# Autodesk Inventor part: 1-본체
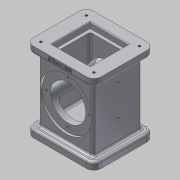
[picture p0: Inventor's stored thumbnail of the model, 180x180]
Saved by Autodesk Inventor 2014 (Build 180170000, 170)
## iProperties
Created: 2017-08
Part Number: 1-본체
Material: 알루미늄 6061
Document SubType Name: Modeling
Designer: 601-04
Density: 2.71 g/cm^3
Appearance: 알루미늄 - 평지
Mass: 871.037 g
Surface Area: 645.524 cm^2
Volume: 321.416 cm^3
Author: 601-04
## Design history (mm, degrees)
sketch "스케치1"
  geometry: L1 (-46, 41)-(46, 41); L2 (46, 41)-(46, -41); L3 (46, -41)-(-46, -41); L4 (-46, -41)-(-46, 41); L5 (-46, 41)-(46, -41); L6 (46, 41)-(-46, -41); 1 further point
  constraints: 12 end point, 2 midpoint, 2 parallel, 1 horizontal, 1 perpendicular
  dimensions: "d0" = 92 distance of L2.end L3.end; "d1" = 82 distance of L1.end L2.end
extrude "돌출1" new body sketch "스케치1" distance "d2" = 10; taper "d3" = 0 deg
sketch "스케치2"
  geometry: L1 (-37, 33)-(37, 33); L2 (37, 33)-(37, -33); L3 (37, -33)-(-37, -33); L4 (-37, -33)-(-37, 33); L5 (-37, 33)-(37, -33); L6 (37, 33)-(-37, -33); 1 further point
  constraints: 12 end point, 2 midpoint, 2 parallel, 1 horizontal, 1 perpendicular
  dimensions: "d4" = 74 distance of L2.end L3.end; "d5" = 66 distance of L1.end L2.end
extrude "돌출2" join sketch "스케치2" distance "d6" = 88; taper "d7" = 0 deg
sketch "스케치3"
  geometry: L1 (-46, 41)-(46, 41); L2 (46, 41)-(46, -41); L3 (46, -41)-(-46, -41); L4 (-46, -41)-(-46, 41); L5 (-46, 41)-(46, -41); L6 (46, 41)-(-46, -41); 1 further point
  constraints: 12 end point, 2 midpoint, 2 parallel, 1 horizontal, 1 perpendicular
  dimensions: "d8" = 92 distance of L2.end L3.end; "d9" = 82 distance of L1.end L2.end
extrude "돌출3" join sketch "스케치3" distance "d10" = 10; taper "d11" = 0 deg
sketch "스케치4"
  geometry: L1 (-22, 22)-(22, 22); L2 (22, 22)-(22, -22); L3 (22, -22)-(-22, -22); L4 (-22, -22)-(-22, 22); L5 (-22, 22)-(22, -22); L6 (22, 22)-(-22, -22); 1 further point
  constraints: 12 end point, 2 midpoint, 2 parallel, 1 horizontal, 1 perpendicular
  dimensions: "d12" = 44 distance of L2.end L3.end; "d13" = 44 distance of L1.end L2.end
extrude "돌출4" cut sketch "스케치4" distance "d14" = 82; taper "d15" = 0 deg
sketch "스케치5"
  geometry: L1 (26, 26)-(-26, 26); L2 (-26, 26)-(-26, -26); L3 (-26, -26)-(26, -26); L4 (26, -26)-(26, 26); L5 (26, 26)-(-26, -26); L6 (-26, 26)-(26, -26); 1 further point
  constraints: 12 end point, 2 midpoint, 2 parallel, 2 perpendicular, 1 horizontal
  dimensions: "d16" = 52 distance of L3.end L2.end
extrude "돌출5" cut sketch "스케치5" distance "d17" = 8; taper "d18" = 0 deg
sketch "스케치6"
  geometry: L1 (-24, 24)-(24, 24); L2 (24, 24)-(24, -24); L3 (24, -24)-(-24, -24); L4 (-24, -24)-(-24, 24); L5 (-24, 24)-(24, -24); L6 (24, 24)-(-24, -24); 1 further point
  constraints: 12 end point, 2 midpoint, 2 parallel, 1 horizontal, 1 perpendicular
  dimensions: "d19" = 48 distance of L2.end L3.end; "d20" = 48 distance of L1.end L2.end
extrude "돌출6" cut sketch "스케치6" distance "d21" = 16; taper "d22" = 0 deg
sketch "스케치7"
  geometry: C1 r 24 at (37, 44); 1 further point
  constraints: 1 centre point, 1 vertical alignment
  dimensions: "d23" = 48 diameter of C1; "d24" = 54 distance of point (37, -10) C1.centre
extrude "돌출7" cut sketch "스케치7" stored distance "d25" = 8; taper "d26" = 0 deg
sketch "스케치8"
  geometry: C1 r 24 at (37, 44) reference; C2 r 35 at (37, 44); 1 further point
  constraints: 1 centre point, 1 coincident
  dimensions: "d27" = 70 diameter of C2
extrude "돌출8" cut sketch "스케치8" distance "d28" = 3; taper "d29" = 0 deg
fillet "모깎기1" dims "d30" = 10
sketch "스케치9"
  geometry: A1 r 10 centre (36, -31) between (36, -41) and (46, -31) reference; A2 r 10 centre (36, 31) between (46, 31) and (36, 41) reference; A3 r 10 centre (-36, 31) between (-36, 41) and (-46, 31) reference; A4 r 10 centre (-36, -31) between (-46, -31) and (-36, -41) reference; 5 further points
  constraints: 4 coincident
hole "구멍1" sketch "스케치9" at (-36, 31), (36, 31), (36, -31), (-36, -31) diameter "d31" = 3.242; stored, may be unused: countersink angle "d35" = 90 deg, drill point angle "d37" = 118 deg; dims "d32" = 4, "d33" = 4, "d34" = 2, "d36" = 6
sketch "스케치10"
  geometry: A1 r 10 centre (36, 31) between (46, 31) and (36, 41) reference; A2 r 10 centre (-36, 31) between (-36, 41) and (-46, 31) reference; A3 r 10 centre (-36, -31) between (-46, -31) and (-36, -41) reference; A4 r 10 centre (36, -31) between (36, -41) and (46, -31) reference; 5 further points
  constraints: 4 coincident
hole "구멍2" sketch "스케치10" at (-36, 31), (36, 31), (36, -31), (-36, -31) diameter "d38" = 3.242; stored, may be unused: countersink angle "d42" = 90 deg, drill point angle "d44" = 118 deg; dims "d39" = 4, "d40" = 4, "d41" = 2, "d43" = 6
sketch "스케치11" dims "d45" = 58
  geometry: C1 r 35 at (0, 0) reference; 3 further points
  constraints: 2 vertical alignment, 1 coincident, 2 other
hole "구멍3" sketch "스케치11" at (0, 29) diameter "d46" = 3.242; stored, may be unused: countersink angle "d50" = 90 deg, drill point angle "d52" = 118 deg; dims "d47" = 4, "d48" = 4, "d49" = 2, "d51" = 6
sketch "스케치12"
  geometry: L1 (0, 66)-(0, 0) reference; L2 (-88, 66)-(-88, 0) reference; L3 (-88, 33)-(0, 33); L4 (10, 64)-(10, 2) reference; 3 further points
  constraints: 2 end point, 2 midpoint, 2 point on line
  dimensions: "d56" = 38 distance from line of L4 point (-28, 33); "d57" = 42 distance of point (-70, 33) point (-28, 33)
hole "구멍4" sketch "스케치12" at (-28, 33), (-70, 33) diameter "d58" = 4.134; stored, may be unused: countersink angle "d62" = 90 deg, drill point angle "d64" = 118 deg; dims "d59" = 4, "d60" = 4, "d61" = 2, "d63" = 6
fillet "모깎기2" dims "d65" = 3
fillet "모깎기3" dims "d66" = 3
fillet "모깎기4" dims "d67" = 3
chamfer "모따기1" distance "d68" = 1; stored, may be unused: second distance "d69" = 2, angle "d70" = 45 deg
fillet "모깎기5" dims "d71" = 3
sketch "스케치13"
  geometry: L1 (0, 0)-(72, 0) reference; L2 (-10, 0)-(-10, -7) reference; 2 further points
  constraints: 1 other
  dimensions: "d72" = 46 distance from line of L2 point (36, -4); "d73" = 4 distance from line of L1 point (36, -4)
feature "엠보싱1" sketch "스케치13" dims "d0" = 92, "d1" = 82, "d8" = 92, "d9" = 82, "d74" = 0.5, "d75" = 0
node "솔리드1"
pattern_circular "원형 패턴1" dims angle "d54" = 360 deg
mirror "대칭1"
